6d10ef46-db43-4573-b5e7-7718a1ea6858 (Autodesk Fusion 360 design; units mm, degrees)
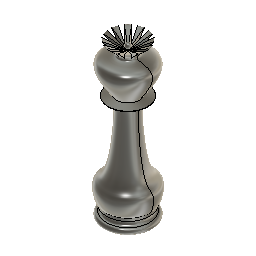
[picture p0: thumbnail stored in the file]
sketch "Sketch1" plane through (0, 0, 0) normal (0, 1, 0) x axis (1, 0, 0)
  line L1 (10, 0) -> (0, 0)
  line L2 (0, -66.9953) -> (0, 0)
  line L3 (9.8472, -6.3241) -> (9.8472, -4.9953)
  curve K1 (5.1077, -46.9149) -> (9.8472, -6.3241)
  line L4 (8.9781, -48.0066) -> (5.1077, -46.9149)
  line L5 (8.9781, -48.1868) -> (8.9781, -48.0066)
  line L6 (5.2744, -48.9162) -> (8.9781, -48.1868)
  curve K2 (0, -66.9953) -> (5.2744, -48.9162)
  arc A1 centre (10, -1.2523) radius 1.2523 clockwise from (10, 0) to (9.8472, -2.4953)
  arc A2 centre (9.7339, -3.7453) radius 1.2551 clockwise from (9.8472, -4.9953) to (9.8472, -2.4953)
  point P1 (0, 0)
  point P2 (0, 0)
  point P4 (0, 0)
  point P3 (10, 0)
  point P5 (9.8472, -2.4953)
  point P7 (9.8472, -4.9953)
  coincident P1 P2
  horizontal L1
  coincident P1 P4
  perpendicular L1 L2
  tangent L1 A1
  parallel L2 L3
  parallel L2 L5
  dimension "d1" distance P2 P3 = 10
  dimension "d3" distance P3 P5 = 2.5
  dimension "d4" distance P5 P7 = 2.5
revolve "Revolve1" sketch "Sketch1" AlongAngle 360
work_plane "WorkPlane1" AlongDistance -10.266
sketch "Sketch2" plane through (0, -10.266, 0) normal (0, 1, 0) x axis (1, 0, 0)
  curve K1 (0, -65.8386) -> (0, -72.3953)
  line L1 (0, -72.3953) -> (0, -65.8386)
  curve K2 (0, -65.8386) -> (0, -72.3953)
  curve K3 (-0.6876, -72.3854) -> (0.6876, -72.4053)
  curve K4 (0.2625, -64.9277) -> (-0.2625, -66.7495)
  curve K5 (0.6876, -72.3854) -> (-0.6876, -72.4053)
  curve K6 (-0.2625, -64.9277) -> (0.2625, -66.7495)
  point P2 (0, -72.3953)
  point P4 (0, -65.8386)
  point P5 (0, -72.3953)
  point P3 (-0.9491, -71.4382)
  point P6 (0.9491, -71.4382)
  point P7 (0, -65.8386)
  point P8 (0.6876, -72.4053)
  point P12 (-0.6876, -72.4053)
  point P9 (-0.6876, -72.3854)
  point P13 (0.6876, -72.3854)
  point P10 (-0.2625, -66.7495)
  point P14 (0.2625, -66.7495)
  point P11 (0.2625, -64.9277)
  point P15 (-0.2625, -64.9277)
  vertical L1
  midpoint P2 K3
  midpoint P4 K4
  symmetric P2 L1 P5
  symmetric P3 L1 P6
  symmetric P4 L1 P7
  symmetric L1 P8 P12
  symmetric L1 P9 P13
  symmetric L1 P10 P14
  symmetric L1 P11 P15
extrude "Extrude1" cut sketch "Sketch2" profile of K1 L1 K2 along normal blind 9.748
circular_pattern "C-Pattern1" countU 12 TotalAngle 360
sketch "Sketch3" plane through (0, 0, 0) normal (0, 1, 0) x axis (1, 0, 0)
  line L1 (0.0289, -66.7704) -> (0.0289, -69.2985)
  arc A1 centre (0.0289, -68.0344) radius 1.2641 clockwise from (0.0289, -69.2985) to (0.0289, -66.7704)
  vertical L1
revolve "Revolve2" sketch "Sketch3" AlongAngle 360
